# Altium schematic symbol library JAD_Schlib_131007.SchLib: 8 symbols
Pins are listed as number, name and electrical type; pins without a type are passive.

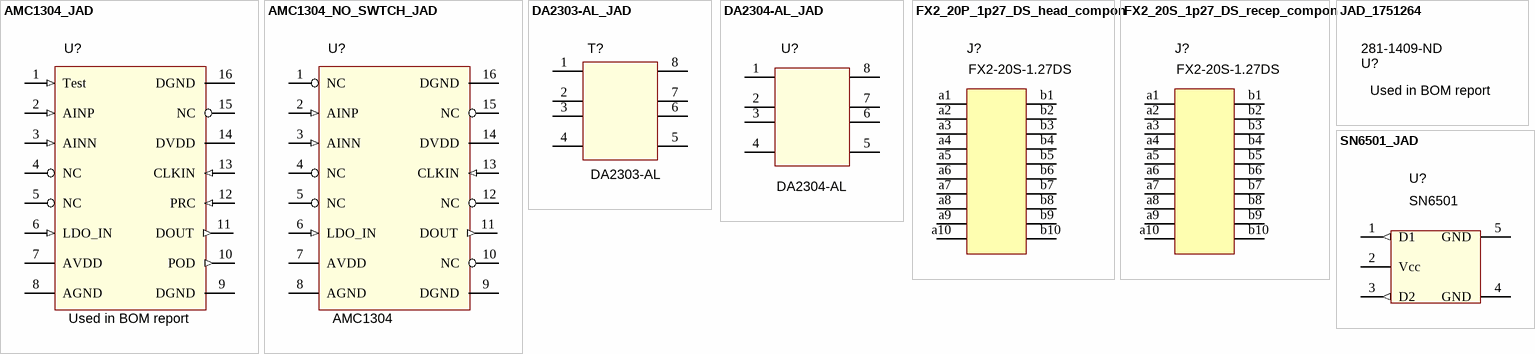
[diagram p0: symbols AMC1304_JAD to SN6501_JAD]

## AMC1304_JAD
designator U?, comment Used in BOM report
JAD-created AMC1304Mx in 16-pin DW (SOIC) package; SymbolVersion: use current date i.e. 2008-05-20; SymbolCreator: Use a-id; CompType: Used in some BOM reports.  Useful for finding later.; U/M: EA, IN, or GM
footprint DW0016_HV_ISO_JAD (SOIC, 16-Leads, Body 10.5x7.6mm (max), Pitch 1.27mm, IPC High Density)
pins: 1 Test (in), 2 AINP (in), 3 AINN (in), 4 NC (hiz), 5 NC (hiz), 6 LDO_IN (in), 7 AVDD (power), 8 AGND (power), 9 DGND (power), 10 POD (out), 11 DOUT (out), 12 PRC (in), 13 CLKIN (in), 14 DVDD (power), 15 NC (hiz), 16 DGND (power)

## AMC1304_NO_SWTCH_JAD
designator U?, comment AMC1304
JAD-created AMC1304Mx in 16-pin DW (SOIC) package; Manufacturer: Used in BOM report; SymbolVersion: use current date i.e. 2008-05-20; SymbolCreator: Use a-id; CompType: Used in some BOM reports.  Useful for finding later.; U/M: EA, IN, or GM
footprint DW0016A_N (SOIC, 16-Leads, Body 10.3x7.5mm, Pitch 1.27mm, IPC Medium Density)
pins: 1 NC (hiz), 2 AINP (in), 3 AINN (in), 4 NC (hiz), 5 NC (hiz), 6 LDO_IN (in), 7 AVDD (power), 8 AGND (power), 9 DGND (power), 10 NC (hiz), 11 DOUT (out), 12 NC (hiz), 13 CLKIN (in), 14 DVDD (power), 15 NC (hiz), 16 DGND (power)

## DA2303-AL_JAD
designator T?, comment DA2303-AL
Manufacturer: Used in BOM report; SymbolVersion: use current date i.e. 2008-05-20; SymbolCreator: Use a-id; CompType: Used in some BOM reports.  Useful for finding later.; U/M: EA, IN, or GM
footprint DA230x_land_patt
pins: 1, 2, 3, 4, 5 4, 6 3, 7 2, 8 1

## DA2304-AL_JAD
designator U?, comment DA2304-AL
JAD-made DA2304-AL; Manufacturer: Used in BOM report; SymbolVersion: use current date i.e. 2008-05-20; SymbolCreator: Use a-id; CompType: Used in some BOM reports.  Useful for finding later.; U/M: EA, IN, or GM
footprint DA230x_land_patt
pins: 1, 2, 3, 4, 5 4, 6 3, 7 2, 8 1

## FX2_20P_1p27_DS_head_compon
designator J?, comment FX2-20S-1.27DS
1.27mm Pitch Multi-function Two Piece Connector; Manufacturer: Hirose; SymbolCreator: Use a-id; U/M: EA, IN, or GM
footprint FX2_20P_1p27_DS_head_good (Hirose FX2-20P-1.27DS: CONN HEADER Right Angle 20POS 1.27MM.)
pins: a1, a2, a3, a4, a5, a6, a7, a8, a9, a10, b1, b2, b3, b4, b5, b6, b7, b8, b9, b10

## FX2_20S_1p27_DS_recep_compon
designator J?, comment FX2-20S-1.27DS
1.27mm Pitch Multi-function Two Piece Connector; Manufacturer: Hirose; SymbolCreator: Use a-id; U/M: EA, IN, or GM
footprint FX2_20S_1p27_DS_recept_good (Hirose FX2-20P-1.27DS: CONN receptacle Right Angle 20POS 1.27MM.)
pins: a1, a2, a3, a4, a5, a6, a7, a8, a9, a10, b1, b2, b3, b4, b5, b6, b7, b8, b9, b10

## JAD_1751264
designator U?, comment Used in BOM report  Supplier Part Number 1: 281-1409-ND
SymbolVersion: use current date i.e. 2008-05-20; SymbolCreator: Use a-id; CompType: Used in some BOM reports.  Useful for finding later.; U/M: EA, IN, or GM

## SN6501_JAD
designator U?, comment SN6501
JAD-made SN6501; Manufacturer: Used in BOM report; SymbolVersion: use current date i.e. 2008-05-20; SymbolCreator: Use a-id; CompType: Used in some BOM reports.  Useful for finding later.; U/M: EA, IN, or GM
footprint DBV0005A_N (SOT23, 5-Leads, Body 2.9x1.6mm, Pitch 0.95mm, Lead Span 2.8mm, IPC Medium Density)
pins: 1 D1 (out), 2 Vcc (power), 3 D2 (out), 4 GND (power), 5 GND (power)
